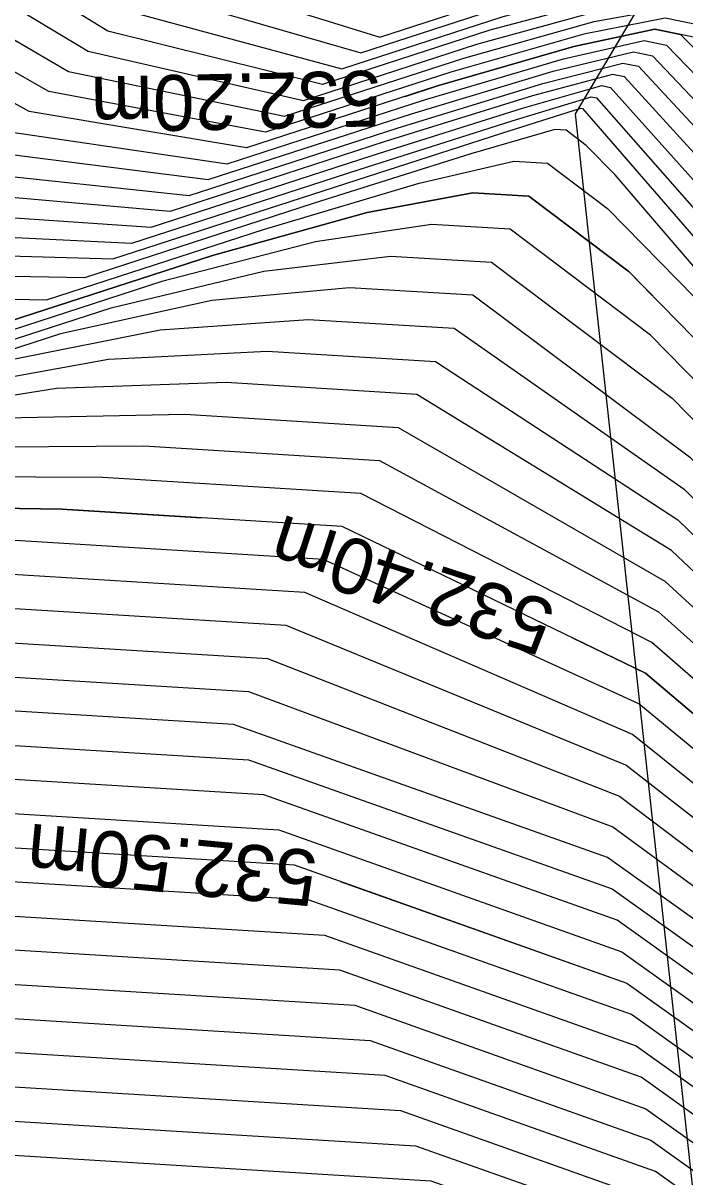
# Model space of a CAD drawing. Extents: x -866683 to -866410, y -1041951 to -1040252.
# Drawn here: x -866459.69 to -866456.13, y -1041918.11 to -1041911.91 of the extents above; entities that cross this region are included whole.
import ezdxf

# ---------------------------------------------------------------- set-up
doc = ezdxf.new("R2010")
doc.units = 0
for name, color, linetype in [('BODY', 7, 'Continuous'), ('BODY_2016', 7, 'Continuous'), ('BREAKLINE', 7, 'Continuous'), ('V-VEDL', 7, 'Continuous'), ('V_po_cm', 7, 'Continuous')]:
    doc.layers.add(name, color=color, linetype=linetype)

msp = doc.modelspace()

# ---------------------------------------------------------------- linework, layer by layer
at = {"layer": 'BREAKLINE'}
msp.add_lwpolyline([(-866451.679, -1041950.508), (-866455.618, -1041922.473), (-866456.719, -1041912.396), (-866455.207, -1041909.853), (-866453.752, -1041908.342), (-866450, -1041907.538), (-866447.7, -1041908.076), (-866445.165, -1041909.459), (-866437.422, -1041915.176), (-866426.565, -1041925.108), (-866438.22, -1041915.868), (-866445.312, -1041910.554), (-866447.7, -1041908.076)], dxfattribs=at)
at = {"layer": 'V-VEDL'}
for points in [[(-866456.0139, -1041911.9987), (-866456.2926, -1041911.9417), (-866456.7284, -1041912.0338), (-866457.4606, -1041912.2465), (-866458.4892, -1041912.5798), (-866459.6567, -1041912.3845), (-866460.9629, -1041911.6604), (-866463.8529, -1041909.155)], [(-866453.6171, -1041916.4043), (-866455.6514, -1041914.0403), (-866456.43, -1041913.2461), (-866456.9701, -1041912.8398), (-866457.2717, -1041912.8213), (-866457.8386, -1041912.9275), (-866458.6706, -1041913.1584), (-866459.7678, -1041913.5139), (-866460.795, -1041913.4946), (-866461.7521, -1041913.1004), (-866463.5263, -1041911.5623)], [(-866449.9912, -1041921.3637), (-866450.5495, -1041921.294), (-866451.362, -1041920.5428), (-866452.7079, -1041919.0752), (-866454.5872, -1041916.8912), (-866456.3427, -1041915.4044), (-866457.9746, -1041914.6148), (-866459.4827, -1041914.5224), (-866460.6238, -1041914.5048), (-866461.3979, -1041914.5619), (-866461.805, -1041914.6938), (-866462.1862, -1041914.6867), (-866462.5414, -1041914.5404), (-866463.1997, -1041913.9697)], [(-866462.1678, -1041916.1944), (-866458.2322, -1041916.4356), (-866456.4431, -1041917.0707), (-866454.8326, -1041918.2202), (-866453.4008, -1041919.8842), (-866452.2221, -1041921.0215), (-866451.2966, -1041921.6321), (-866449.952, -1041921.7999)]]:
    msp.add_lwpolyline(points, dxfattribs=at)
at = {"layer": 'V_po_cm'}
for points in [[(-866463.9732, -1041919.6692), (-866464.0834, -1041917.5641), (-866464.1965, -1041915.6057), (-866464.3127, -1041913.794), (-866464.4318, -1041912.1292), (-866464.4801, -1041910.8978), (-866464.4575, -1041910.1), (-866464.364, -1041909.7358), (-866464.2807, -1041909.2817), (-866464.2076, -1041908.7376), (-866464.1445, -1041908.1037), (-866463.4907, -1041908.2115), (-866462.2459, -1041909.0611), (-866460.4104, -1041910.6524), (-866458.9188, -1041911.6265), (-866457.7712, -1041911.9833), (-866456.9676, -1041911.7229), (-866456.342, -1041911.5677), (-866455.8946, -1041911.5176), (-866455.6252, -1041911.5727), (-866455.1094, -1041912), (-866454.3471, -1041912.7994), (-866452.3298, -1041915.1426)], [(-866463.9523, -1041919.7205), (-866464.0638, -1041917.5906), (-866464.1762, -1041915.6382), (-866464.2896, -1041913.8635), (-866464.4038, -1041912.2663), (-866464.4483, -1041911.0776), (-866464.4228, -1041910.2975), (-866464.3275, -1041909.926), (-866464.2436, -1041909.4735), (-866464.1711, -1041908.9398), (-866464.11, -1041908.3252), (-866463.476, -1041908.4297), (-866462.2691, -1041909.2535), (-866460.4893, -1041910.7964), (-866459.0242, -1041911.7348), (-866457.8738, -1041912.0686), (-866457.038, -1041911.7977), (-866456.3972, -1041911.6343), (-866455.9514, -1041911.5782), (-866455.7006, -1041911.6295), (-866455.1738, -1041912.0814), (-866454.3711, -1041912.9338), (-866452.2137, -1041915.4397)], [(-866463.9314, -1041919.7718), (-866464.0442, -1041917.6171), (-866464.1559, -1041915.6708), (-866464.2665, -1041913.9329), (-866464.3759, -1041912.4034), (-866464.4164, -1041911.2574), (-866464.3881, -1041910.495), (-866464.291, -1041910.1162), (-866464.2065, -1041909.6652), (-866464.1346, -1041909.142), (-866464.0754, -1041908.5467), (-866463.4613, -1041908.6479), (-866462.2922, -1041909.4459), (-866460.5683, -1041910.9404), (-866459.1296, -1041911.8431), (-866457.9764, -1041912.1538), (-866457.1084, -1041911.8725), (-866456.4524, -1041911.7008), (-866456.0083, -1041911.6388), (-866455.7761, -1041911.6863), (-866455.2383, -1041912.1627), (-866454.3951, -1041913.0681), (-866452.0976, -1041915.7367)], [(-866451.9815, -1041916.0338), (-866454.4191, -1041913.2024), (-866455.3028, -1041912.2441), (-866455.8515, -1041911.7431), (-866456.0651, -1041911.6993), (-866456.5076, -1041911.7674), (-866457.1789, -1041911.9473), (-866458.0789, -1041912.239), (-866459.2351, -1041911.9514), (-866460.6472, -1041911.0844), (-866462.3153, -1041909.6382), (-866463.4466, -1041908.8661), (-866464.0408, -1041908.7681), (-866464.0981, -1041909.3442), (-866464.1693, -1041909.857), (-866464.2544, -1041910.3064), (-866464.3535, -1041910.6925), (-866464.3846, -1041911.4372), (-866464.3479, -1041912.5405), (-866464.2433, -1041914.0023), (-866464.1356, -1041915.7034), (-866464.0247, -1041917.6436), (-866463.9105, -1041919.8231)], [(-866463.8897, -1041919.8744), (-866464.0051, -1041917.6701), (-866464.1153, -1041915.7359), (-866464.2202, -1041914.0717), (-866464.32, -1041912.6776), (-866464.3528, -1041911.617), (-866464.3188, -1041910.89), (-866464.2179, -1041910.4967), (-866464.1322, -1041910.0488), (-866464.0616, -1041909.5464), (-866464.0062, -1041908.9896), (-866463.4319, -1041909.0843), (-866462.3385, -1041909.8306), (-866460.7261, -1041911.2284), (-866459.3405, -1041912.0596), (-866458.1815, -1041912.3242), (-866457.2493, -1041912.0221), (-866456.5628, -1041911.834), (-866456.122, -1041911.7599), (-866455.9269, -1041911.7998), (-866455.3673, -1041912.3255), (-866454.443, -1041913.3368), (-866451.8653, -1041916.3308)], [(-866463.8688, -1041919.9257), (-866463.9855, -1041917.6967), (-866464.0949, -1041915.7685), (-866464.1971, -1041914.1412), (-866464.292, -1041912.8147), (-866464.321, -1041911.7968), (-866464.2841, -1041911.0875), (-866464.1814, -1041910.6869), (-866464.095, -1041910.2406), (-866464.0251, -1041909.7486), (-866463.9717, -1041909.2111), (-866463.4172, -1041909.3025), (-866462.3616, -1041910.023), (-866460.805, -1041911.3724), (-866459.4459, -1041912.1679), (-866458.2841, -1041912.4094), (-866457.3197, -1041912.0969), (-866456.618, -1041911.9006), (-866456.1789, -1041911.8205), (-866456.0024, -1041911.8566), (-866455.4317, -1041912.4068), (-866454.467, -1041913.4711), (-866451.7492, -1041916.6279)], [(-866451.6331, -1041916.9249), (-866454.491, -1041913.6054), (-866455.4962, -1041912.4882), (-866456.0778, -1041911.9134), (-866456.2357, -1041911.8811), (-866456.6732, -1041911.9672), (-866457.3901, -1041912.1717), (-866458.3867, -1041912.4946), (-866459.5513, -1041912.2762), (-866460.884, -1041911.5164), (-866462.3847, -1041910.2153), (-866463.4024, -1041909.5207), (-866463.9371, -1041909.4325), (-866463.9886, -1041909.9508), (-866464.0579, -1041910.4324), (-866464.1448, -1041910.8771), (-866464.2495, -1041911.285), (-866464.2892, -1041911.9766), (-866464.264, -1041912.9518), (-866464.174, -1041914.2106), (-866464.0746, -1041915.8011), (-866463.9659, -1041917.7232), (-866463.8479, -1041919.9769)], [(-866463.8062, -1041920.0795), (-866463.9268, -1041917.7762), (-866464.034, -1041915.8662), (-866464.1278, -1041914.3495), (-866464.2081, -1041913.226), (-866464.2256, -1041912.3362), (-866464.1801, -1041911.68), (-866464.0717, -1041911.2575), (-866463.9836, -1041910.8159), (-866463.9156, -1041910.3552), (-866463.8679, -1041909.8755), (-866463.373, -1041909.9571), (-866462.431, -1041910.6001), (-866461.0418, -1041911.8044), (-866459.7621, -1041912.4928), (-866458.5918, -1041912.665), (-866457.531, -1041912.3213), (-866456.7835, -1041912.1004), (-866456.3494, -1041912.0022), (-866456.2287, -1041912.0269), (-866455.6252, -1041912.6509), (-866454.5389, -1041913.8741), (-866451.4009, -1041917.519)], [(-866463.7853, -1041920.1308), (-866463.9072, -1041917.8027), (-866464.0137, -1041915.8988), (-866464.1046, -1041914.4189), (-866464.1802, -1041913.3631), (-866464.1938, -1041912.516), (-866464.1455, -1041911.8775), (-866464.0352, -1041911.4477), (-866463.9464, -1041911.0077), (-866463.8791, -1041910.5574), (-866463.8334, -1041910.0969), (-866463.3583, -1041910.1753), (-866462.4541, -1041910.7924), (-866461.1207, -1041911.9484), (-866459.8675, -1041912.601), (-866458.6944, -1041912.7503), (-866457.6014, -1041912.3961), (-866456.8387, -1041912.1669), (-866456.4063, -1041912.0628), (-866456.3041, -1041912.0837), (-866455.6896, -1041912.7323), (-866454.5629, -1041914.0085), (-866451.2847, -1041917.8161)], [(-866463.7645, -1041920.1821), (-866463.8876, -1041917.8293), (-866463.9933, -1041915.9313), (-866464.0815, -1041914.4883), (-866464.1522, -1041913.5002), (-866464.162, -1041912.6958), (-866464.1108, -1041912.075), (-866463.9987, -1041911.638), (-866463.9093, -1041911.1995), (-866463.8427, -1041910.7596), (-866463.7988, -1041910.3184), (-866463.3436, -1041910.3934), (-866462.4773, -1041910.9848), (-866461.1996, -1041912.0924), (-866459.9729, -1041912.7093), (-866458.7969, -1041912.8355), (-866457.6718, -1041912.4709), (-866456.8939, -1041912.2335), (-866456.4631, -1041912.1234), (-866456.3795, -1041912.1405), (-866455.7541, -1041912.8136), (-866454.5868, -1041914.1428), (-866451.1686, -1041918.1132)], [(-866451.0525, -1041918.4102), (-866454.6108, -1041914.2771), (-866455.8186, -1041912.895), (-866456.455, -1041912.1973), (-866456.52, -1041912.184), (-866456.9491, -1041912.3001), (-866457.7423, -1041912.5457), (-866458.8995, -1041912.9207), (-866460.0783, -1041912.8176), (-866461.2786, -1041912.2364), (-866462.5004, -1041911.1772), (-866463.3289, -1041910.6116), (-866463.7642, -1041910.5399), (-866463.8062, -1041910.9618), (-866463.8721, -1041911.3913), (-866463.9621, -1041911.8282), (-866464.0761, -1041912.2725), (-866464.1302, -1041912.8756), (-866464.1243, -1041913.6373), (-866464.0584, -1041914.5578), (-866463.973, -1041915.9639), (-866463.8681, -1041917.8558), (-866463.7436, -1041920.2334)], [(-866463.7227, -1041920.2847), (-866463.8485, -1041917.8823), (-866463.9527, -1041915.9965), (-866464.0353, -1041914.6272), (-866464.0963, -1041913.7744), (-866464.0983, -1041913.0554), (-866464.0414, -1041912.47), (-866463.9256, -1041912.0184), (-866463.835, -1041911.5831), (-866463.7697, -1041911.164), (-866463.7296, -1041910.7613), (-866463.3142, -1041910.8298), (-866462.5235, -1041911.3695), (-866461.3575, -1041912.3804), (-866460.1837, -1041912.9259), (-866459.0021, -1041913.0059), (-866457.8127, -1041912.6205), (-866457.0043, -1041912.3667), (-866456.5769, -1041912.2446), (-866456.5304, -1041912.2541), (-866455.883, -1041912.9764), (-866454.6348, -1041914.4115), (-866450.9364, -1041918.7073)], [(-866463.7019, -1041920.3359), (-866463.8289, -1041917.9088), (-866463.9324, -1041916.029), (-866464.0122, -1041914.6966), (-866464.0683, -1041913.9116), (-866464.0665, -1041913.2352), (-866464.0068, -1041912.6675), (-866463.889, -1041912.2086), (-866463.7978, -1041911.7748), (-866463.7332, -1041911.3662), (-866463.695, -1041910.9828), (-866463.2995, -1041911.048), (-866462.5467, -1041911.5619), (-866461.4364, -1041912.5244), (-866460.2891, -1041913.0342), (-866459.1046, -1041913.0911), (-866457.8831, -1041912.6953), (-866457.0595, -1041912.4333), (-866456.6337, -1041912.3051), (-866456.6058, -1041912.3108), (-866455.9475, -1041913.0577), (-866454.6587, -1041914.5458), (-866450.8202, -1041919.0043)], [(-866463.681, -1041920.3872), (-866463.8094, -1041917.9353), (-866463.912, -1041916.0616), (-866463.989, -1041914.766), (-866464.0404, -1041914.0487), (-866464.0347, -1041913.415), (-866463.9721, -1041912.865), (-866463.8525, -1041912.3988), (-866463.7607, -1041911.9666), (-866463.6967, -1041911.5684), (-866463.6605, -1041911.2043), (-866463.2848, -1041911.2662), (-866462.5698, -1041911.7543), (-866461.5153, -1041912.6684), (-866460.3945, -1041913.1424), (-866459.2072, -1041913.1763), (-866457.9535, -1041912.7701), (-866457.1147, -1041912.4999), (-866456.6906, -1041912.3657), (-866456.6813, -1041912.3676), (-866456.012, -1041913.1391), (-866454.6827, -1041914.6801), (-866450.7041, -1041919.3014)], [(-866457.6353, -1041912.3031), (-866457.4606, -1041912.2465), (-866456.7284, -1041912.0338), (-866456.2926, -1041911.9417), (-866456.1532, -1041911.9702), (-866455.5607, -1041912.5695), (-866454.5149, -1041913.7398), (-866454.3758, -1041913.9013)], [(-866463.5766, -1041920.6437), (-866463.7115, -1041918.0679), (-866463.8104, -1041916.2244), (-866463.8735, -1041915.1132), (-866463.9006, -1041914.7342), (-866463.8757, -1041914.314), (-866463.7987, -1041913.8526), (-866463.6698, -1041913.3499), (-866463.575, -1041912.9255), (-866463.5142, -1041912.5794), (-866463.4876, -1041912.3116), (-866463.2113, -1041912.3572), (-866462.6855, -1041912.7161), (-866461.91, -1041913.3884), (-866461.0732, -1041913.733), (-866460.1752, -1041913.7499), (-866459.216, -1041913.4391), (-866458.3956, -1041913.2429), (-866457.7139, -1041913.1615), (-866457.171, -1041913.1948), (-866456.1988, -1041913.9262), (-866454.7973, -1041915.3557), (-866452.9665, -1041917.4833), (-866451.6335, -1041919.0324)], [(-866450.0304, -1041921.0569), (-866454.4154, -1041915.9609), (-866456.0982, -1041914.2487), (-866457.2714, -1041913.3723), (-866457.935, -1041913.3316), (-866458.6741, -1041913.4007), (-866459.4888, -1041913.5794), (-866460.379, -1041913.8679), (-866461.2123, -1041913.8522), (-866461.9889, -1041913.5324), (-866462.7086, -1041912.9085), (-866463.1966, -1041912.5753), (-866463.453, -1041912.5331), (-866463.4777, -1041912.7816), (-866463.5378, -1041913.1173), (-866463.6333, -1041913.5401), (-866463.7641, -1041914.0501), (-866463.8439, -1041914.4938), (-866463.8726, -1041914.8713), (-866463.8503, -1041915.1826), (-866463.7901, -1041916.257), (-866463.6919, -1041918.0944), (-866463.5558, -1041920.6949)], [(-866450.588, -1041919.5984), (-866454.2618, -1041915.3313), (-866455.5541, -1041913.8301), (-866456.3021, -1041912.9613), (-866456.5055, -1041912.7249), (-866456.6612, -1041912.566), (-866456.7692, -1041912.4848), (-866456.8295, -1041912.4811), (-866457.2815, -1041912.612), (-866458.1251, -1041912.8776), (-866459.3604, -1041913.2779), (-866460.5167, -1041913.2562)], [(-866460.6559, -1041913.3754), (-866459.5641, -1041913.3959), (-866458.3978, -1041913.018), (-866457.56, -1041912.7697), (-866457.0506, -1041912.6512), (-866456.8697, -1041912.6623), (-866456.5456, -1041912.9061), (-866456.0784, -1041913.3826), (-866455.4682, -1041914.0918), (-866454.574, -1041915.1306), (-866453.3959, -1041916.4992), (-866450.4719, -1041919.8955)], [(-866463.6724, -1041918.121), (-866463.7698, -1041916.2896), (-866463.8272, -1041915.2521), (-866463.8447, -1041915.0084), (-866463.812, -1041914.6736), (-866463.7294, -1041914.2476), (-866463.5967, -1041913.7303), (-866463.5007, -1041913.3091), (-866463.4412, -1041912.9838), (-866463.4184, -1041912.7545), (-866463.1819, -1041912.7935), (-866462.7317, -1041913.1008), (-866462.0678, -1041913.6764), (-866461.3515, -1041913.9714), (-866460.5827, -1041913.9859), (-866459.7615, -1041913.7198), (-866458.9526, -1041913.5584), (-866458.1561, -1041913.5017), (-866457.3719, -1041913.5498), (-866456.1332, -1041914.4138), (-866454.4399, -1041916.0938), (-866450.1444, -1041921.0858)], [(-866460.1819, -1041913.5061), (-866459.7678, -1041913.5139), (-866458.6706, -1041913.1584), (-866457.8386, -1041912.9275), (-866457.2717, -1041912.8213), (-866456.9701, -1041912.8398), (-866456.43, -1041913.2461), (-866456.3058, -1041913.3727)], [(-866463.6528, -1041918.1475), (-866463.7495, -1041916.3221), (-866463.8041, -1041915.3215), (-866463.8167, -1041915.1455), (-866463.7802, -1041914.8534), (-866463.6947, -1041914.4451), (-866463.5602, -1041913.9206), (-866463.4635, -1041913.5009), (-866463.4048, -1041913.186), (-866463.3839, -1041912.976), (-866463.1672, -1041913.0117), (-866462.7549, -1041913.2932), (-866462.1467, -1041913.8204), (-866461.4906, -1041914.0906), (-866460.7864, -1041914.1039), (-866460.0342, -1041913.8601), (-866459.2312, -1041913.7161), (-866458.3772, -1041913.6718), (-866457.4723, -1041913.7273), (-866456.1681, -1041914.5789), (-866454.4645, -1041916.2267), (-866450.2585, -1041921.1147)], [(-866451.6641, -1041918.835), (-866452.6136, -1041917.7318), (-866453.8004, -1041916.3528), (-866455.2243, -1041914.698), (-866456.3144, -1041913.5861), (-866457.0706, -1041913.0173), (-866457.4928, -1041912.9914), (-866458.1171, -1041913.0852), (-866458.9433, -1041913.2987), (-866459.9715, -1041913.6319)], [(-866450.3725, -1041921.1436), (-866454.489, -1041916.3596), (-866456.203, -1041914.744), (-866457.5728, -1041913.9048), (-866458.5983, -1041913.8419), (-866459.5097, -1041913.8738), (-866460.307, -1041914.0005), (-866460.9901, -1041914.2219), (-866461.6297, -1041914.2098), (-866462.2257, -1041913.9644), (-866462.778, -1041913.4856), (-866463.1525, -1041913.2299), (-866463.3493, -1041913.1975), (-866463.3683, -1041913.3882), (-866463.4264, -1041913.6927), (-866463.5237, -1041914.1108), (-866463.6601, -1041914.6426), (-866463.7484, -1041915.0332), (-866463.7887, -1041915.2826), (-866463.781, -1041915.3909), (-866463.7291, -1041916.3547), (-866463.6332, -1041918.174)], [(-866463.6136, -1041918.2005), (-866463.7088, -1041916.3873), (-866463.7579, -1041915.4603), (-866463.7608, -1041915.4197), (-866463.7166, -1041915.213), (-866463.6254, -1041914.8401), (-866463.4871, -1041914.301), (-866463.3892, -1041913.8844), (-866463.3318, -1041913.5904), (-866463.3147, -1041913.4189), (-866463.1378, -1041913.4481), (-866462.8011, -1041913.6779), (-866462.3046, -1041914.1084), (-866461.7688, -1041914.3291), (-866461.1939, -1041914.3399), (-866460.5797, -1041914.1408), (-866459.7882, -1041914.0316), (-866458.8194, -1041914.0121), (-866457.6732, -1041914.0823), (-866456.238, -1041914.9091), (-866454.5136, -1041916.4925), (-866450.4865, -1041921.1725)], [(-866463.5914, -1041918.2787), (-866463.6829, -1041916.4704), (-866463.7246, -1041915.5523), (-866463.7165, -1041915.5245), (-866463.6669, -1041915.3335), (-866463.5758, -1041914.9793), (-866463.4431, -1041914.4621), (-866463.3496, -1041914.0665), (-866463.2953, -1041913.7926), (-866463.2801, -1041913.6404), (-866463.1231, -1041913.6663), (-866462.8243, -1041913.8703), (-866462.3835, -1041914.2524), (-866461.9079, -1041914.4483), (-866461.3976, -1041914.4579), (-866460.8524, -1041914.2812), (-866460.0667, -1041914.1893), (-866459.0405, -1041914.1822), (-866457.7737, -1041914.2598), (-866456.2729, -1041915.0742), (-866454.5381, -1041916.6254), (-866450.6006, -1041921.2014)], [(-866450.7146, -1041921.2303), (-866454.5627, -1041916.7583), (-866456.3078, -1041915.2393), (-866457.8741, -1041914.4373), (-866459.2616, -1041914.3523), (-866460.3452, -1041914.347), (-866461.1252, -1041914.4216), (-866461.6013, -1041914.5759), (-866462.0471, -1041914.5675), (-866462.4624, -1041914.3964), (-866462.8474, -1041914.0627), (-866463.1084, -1041913.8845), (-866463.2456, -1041913.8619), (-866463.2588, -1041913.9948), (-866463.3062, -1041914.2341), (-866463.3879, -1041914.5796), (-866463.5038, -1041915.0313), (-866463.5904, -1041915.365), (-866463.6479, -1041915.5806), (-866463.676, -1041915.6781), (-866463.6484, -1041916.6294), (-866463.565, -1041918.4343)], [(-866450.9427, -1041921.2881), (-866454.6117, -1041917.0241), (-866456.3777, -1041915.5695), (-866458.075, -1041914.7923), (-866459.7037, -1041914.6925), (-866460.9023, -1041914.6625), (-866461.6706, -1041914.7023), (-866462.0088, -1041914.8118), (-866462.3253, -1041914.8059), (-866462.6203, -1041914.6844), (-866462.8937, -1041914.4474), (-866463.079, -1041914.3209), (-866463.1764, -1041914.3048), (-866463.1858, -1041914.3992), (-866463.2195, -1041914.5691), (-866463.2775, -1041914.8145), (-866463.3598, -1041915.1353), (-866463.4375, -1041915.4281), (-866463.5105, -1041915.6929), (-866463.579, -1041915.9297), (-866463.5796, -1041916.9473), (-866463.5124, -1041918.7456)], [(-866461.9478, -1041914.6912), (-866461.805, -1041914.6938), (-866461.3979, -1041914.5619), (-866460.6238, -1041914.5048), (-866459.4827, -1041914.5224), (-866458.733, -1041914.5683)], [(-866451.0567, -1041921.317), (-866454.6363, -1041917.157), (-866456.4126, -1041915.7346), (-866458.1755, -1041914.9698), (-866459.9248, -1041914.8626), (-866461.1808, -1041914.8202), (-866461.9433, -1041914.8426), (-866462.2125, -1041914.9298), (-866462.4644, -1041914.9251), (-866462.6992, -1041914.8284), (-866462.9168, -1041914.6398), (-866463.0643, -1041914.5391), (-866463.1418, -1041914.5263), (-866463.1493, -1041914.6014), (-866463.1761, -1041914.7366), (-866463.2223, -1041914.9319), (-866463.2878, -1041915.1873), (-866463.361, -1041915.4597), (-866463.4419, -1041915.7491), (-866463.5304, -1041916.0555), (-866463.5451, -1041917.1063), (-866463.486, -1041918.9013)], [(-866451.1707, -1041921.3459), (-866454.6608, -1041917.2899), (-866456.4475, -1041915.8997), (-866458.2759, -1041915.1473), (-866460.1459, -1041915.0327), (-866461.4593, -1041914.9779), (-866462.2161, -1041914.983), (-866462.4162, -1041915.0478), (-866462.6036, -1041915.0443), (-866462.7781, -1041914.9724), (-866462.9399, -1041914.8321), (-866463.0496, -1041914.7572), (-866463.1073, -1041914.7477), (-866463.1128, -1041914.8036), (-866463.1328, -1041914.9042), (-866463.1671, -1041915.0494), (-866463.2158, -1041915.2393), (-866463.2845, -1041915.4912), (-866463.3732, -1041915.8052), (-866463.4819, -1041916.1813), (-866463.5107, -1041917.2653), (-866463.4597, -1041919.057)], [(-866463.4334, -1041919.2126), (-866463.4763, -1041917.4242), (-866463.4333, -1041916.3072), (-866463.3045, -1041915.8614), (-866463.208, -1041915.5228), (-866463.1438, -1041915.2912), (-866463.1119, -1041915.1668), (-866463.0894, -1041915.0717), (-866463.0763, -1041915.0058), (-866463.0727, -1041914.9692), (-866463.0349, -1041914.9754), (-866462.963, -1041915.0245), (-866462.857, -1041915.1164), (-866462.7427, -1041915.1635), (-866462.6199, -1041915.1658), (-866462.4888, -1041915.1233), (-866461.7378, -1041915.1357), (-866460.367, -1041915.2028), (-866458.3763, -1041915.3248), (-866456.4825, -1041916.0648), (-866454.6854, -1041917.4228), (-866451.2848, -1041921.3748)], [(-866463.407, -1041919.3683), (-866463.4418, -1041917.5832), (-866463.3848, -1041916.433), (-866463.2358, -1041915.9176), (-866463.1315, -1041915.5543), (-866463.0718, -1041915.3432), (-866463.0567, -1041915.2843), (-866463.046, -1041915.2392), (-866463.0398, -1041915.208), (-866463.0381, -1041915.1907), (-866463.0202, -1041915.1936), (-866462.9862, -1041915.2169), (-866462.936, -1041915.2604), (-866462.8818, -1041915.2827), (-866462.8236, -1041915.2838), (-866462.7615, -1041915.2637), (-866462.0164, -1041915.2934), (-866460.5881, -1041915.3729), (-866458.4768, -1041915.5023), (-866456.5174, -1041916.2299), (-866454.7099, -1041917.5557), (-866451.3988, -1041921.4037)], [(-866456.735, -1041915.2146), (-866456.3427, -1041915.4044), (-866454.5872, -1041916.8912), (-866453.6413, -1041917.9905)], [(-866451.5128, -1041921.4326), (-866454.7345, -1041917.6886), (-866456.5462, -1041916.3954), (-866458.559, -1041915.681), (-866462.9865, -1041915.4096)], [(-866462.7819, -1041915.6058), (-866458.4773, -1041915.8696), (-866456.5205, -1041916.5642), (-866454.759, -1041917.8215), (-866451.6269, -1041921.4615)], [(-866451.7409, -1041921.4904), (-866454.7835, -1041917.9544), (-866456.4947, -1041916.733), (-866458.3956, -1041916.0583), (-866462.5772, -1041915.802)], [(-866462.3725, -1041915.9982), (-866458.3139, -1041916.247), (-866456.4689, -1041916.9019), (-866454.8081, -1041918.0873), (-866451.8549, -1041921.5193)], [(-866452.083, -1041921.5771), (-866454.8572, -1041918.3531), (-866456.4173, -1041917.2395), (-866458.1505, -1041916.6243), (-866461.9631, -1041916.3906)], [(-866457.9843, -1041916.5236), (-866456.4431, -1041917.0707), (-866454.8326, -1041918.2202), (-866454.4544, -1041918.6598)], [(-866461.7584, -1041916.5869), (-866458.0689, -1041916.813), (-866456.3915, -1041917.4083), (-866454.8817, -1041918.486), (-866452.197, -1041921.606)], [(-866452.3111, -1041921.6349), (-866454.9063, -1041918.6189), (-866456.3658, -1041917.5772), (-866457.9872, -1041917.0016), (-866461.5538, -1041916.7831)], [(-866461.3491, -1041916.9793), (-866457.9055, -1041917.1903), (-866456.34, -1041917.746), (-866454.9308, -1041918.7518), (-866452.4251, -1041921.6638)], [(-866461.1444, -1041917.1755), (-866457.8238, -1041917.379), (-866456.3142, -1041917.9148), (-866454.9553, -1041918.8847), (-866452.5391, -1041921.6927)], [(-866452.6532, -1041921.7216), (-866454.9799, -1041919.0176), (-866456.2884, -1041918.0836), (-866457.7421, -1041917.5676), (-866460.9397, -1041917.3717)], [(-866460.735, -1041917.5679), (-866457.6604, -1041917.7563), (-866456.2626, -1041918.2524), (-866455.0044, -1041919.1505), (-866452.7672, -1041921.7505)], [(-866460.5304, -1041917.7641), (-866457.5787, -1041917.945), (-866456.2368, -1041918.4213), (-866455.029, -1041919.2834), (-866452.8812, -1041921.7794)], [(-866460.3257, -1041917.9603), (-866457.497, -1041918.1336), (-866456.211, -1041918.5901), (-866455.0535, -1041919.4163), (-866452.9953, -1041921.8083)]]:
    msp.add_lwpolyline(points, dxfattribs=at)

# ---------------------------------------------------------------- texts
at = {"layer": 'BODY'}
msp.add_text('+', height=0.001, rotation=360, dxfattribs=at).set_placement((-866456.719, -1041912.396))
at = {"layer": 'BODY_2016'}
msp.add_text('+', height=0.001, rotation=360, dxfattribs=at).set_placement((-866456.719, -1041912.396))
at = {"layer": 'V_po_cm'}
for s, rotation, p in [('532.20m', 181.22693, (-866457.7683, -1041912.1634)), ('532.40m', 162.03156, (-866456.8118, -1041915.0301)), ('532.50m', 174.52722, (-866458.0993, -1041916.3612))]:
    msp.add_text(s, height=0.3, rotation=rotation, dxfattribs=at).set_placement(p)

doc.saveas('drawing.dxf')
